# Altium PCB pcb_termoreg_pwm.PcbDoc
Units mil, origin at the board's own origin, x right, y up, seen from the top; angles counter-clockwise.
Board outline 1865 x 1535 mil, 2 copper layers (Top Layer, Bottom Layer); 28 components, 21 nets, 79 pads, 0 vias.
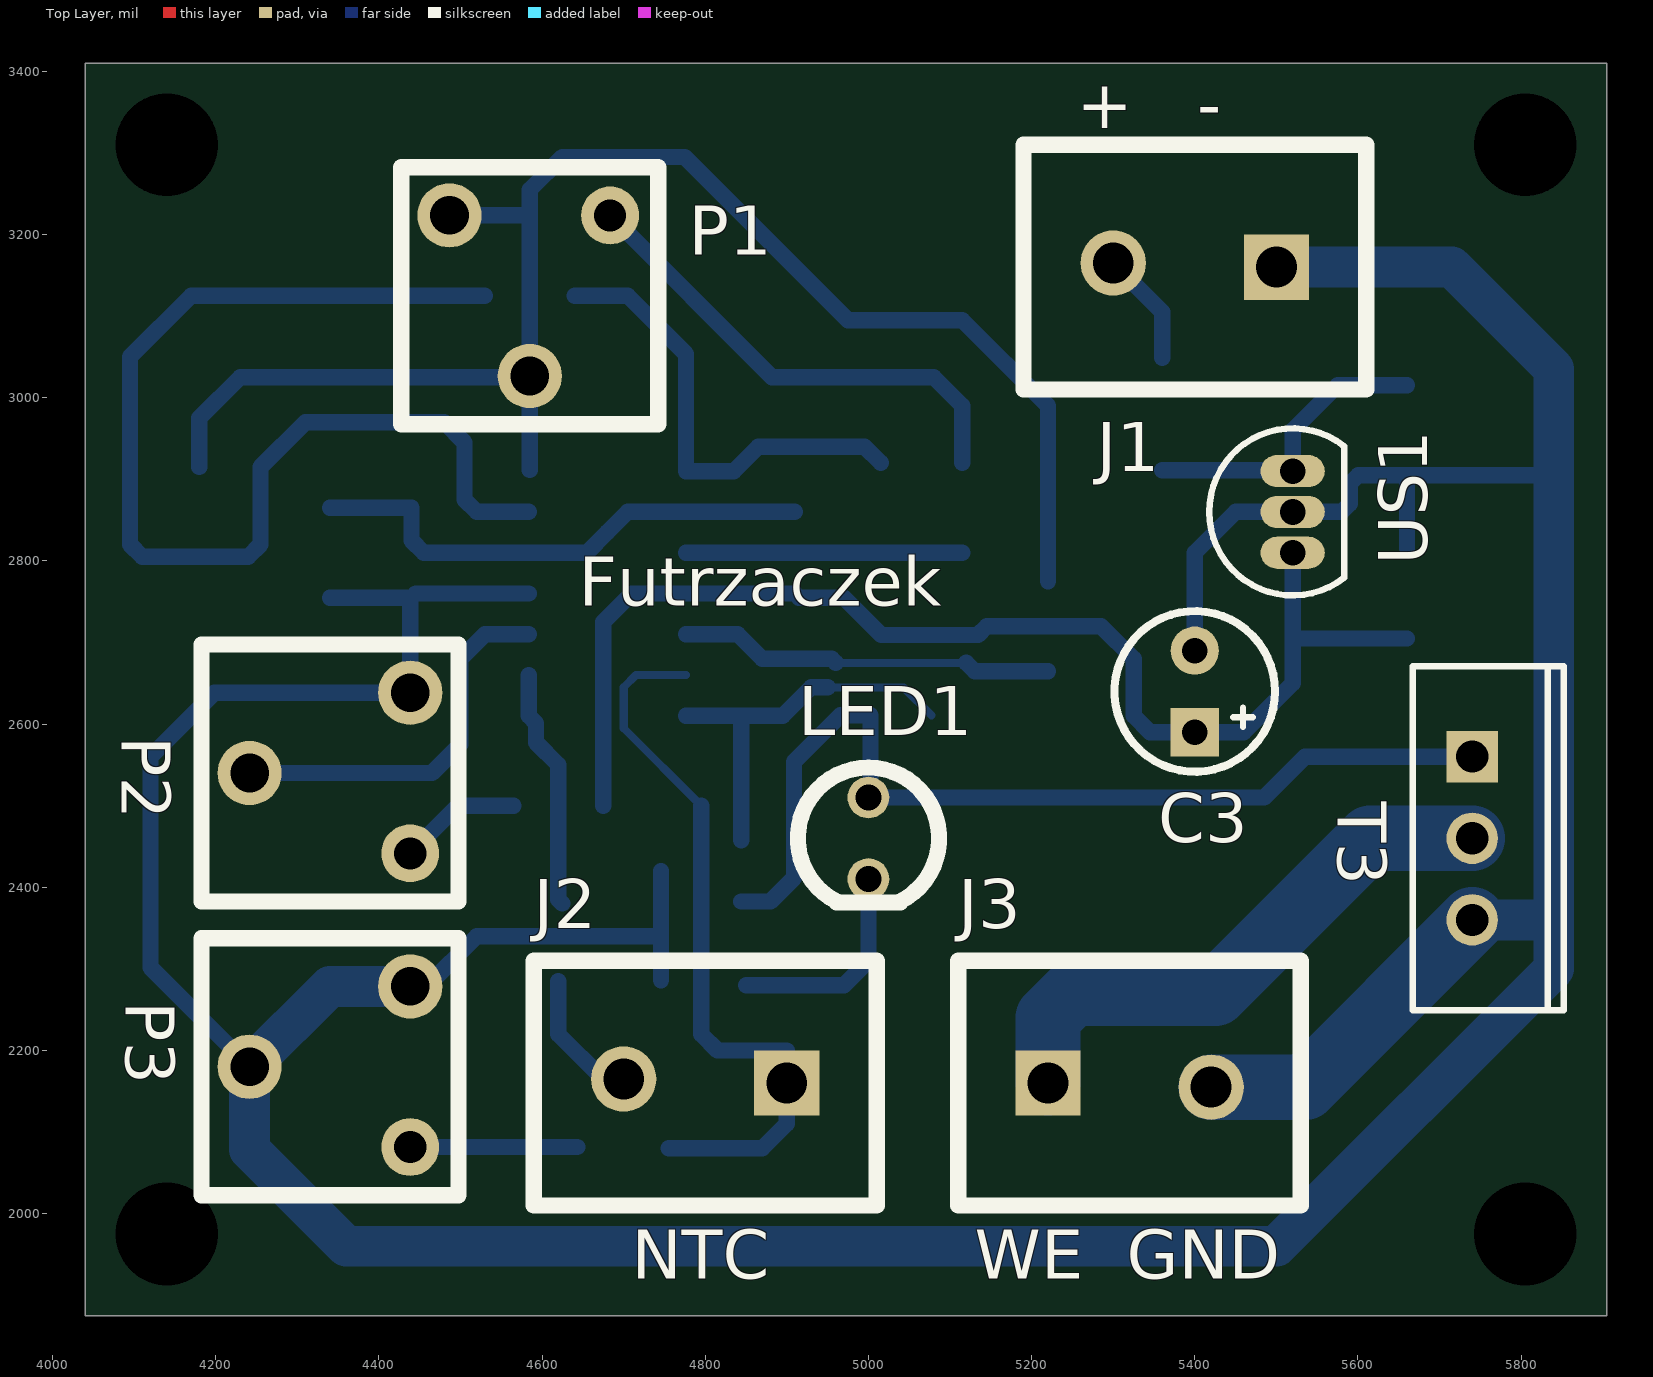
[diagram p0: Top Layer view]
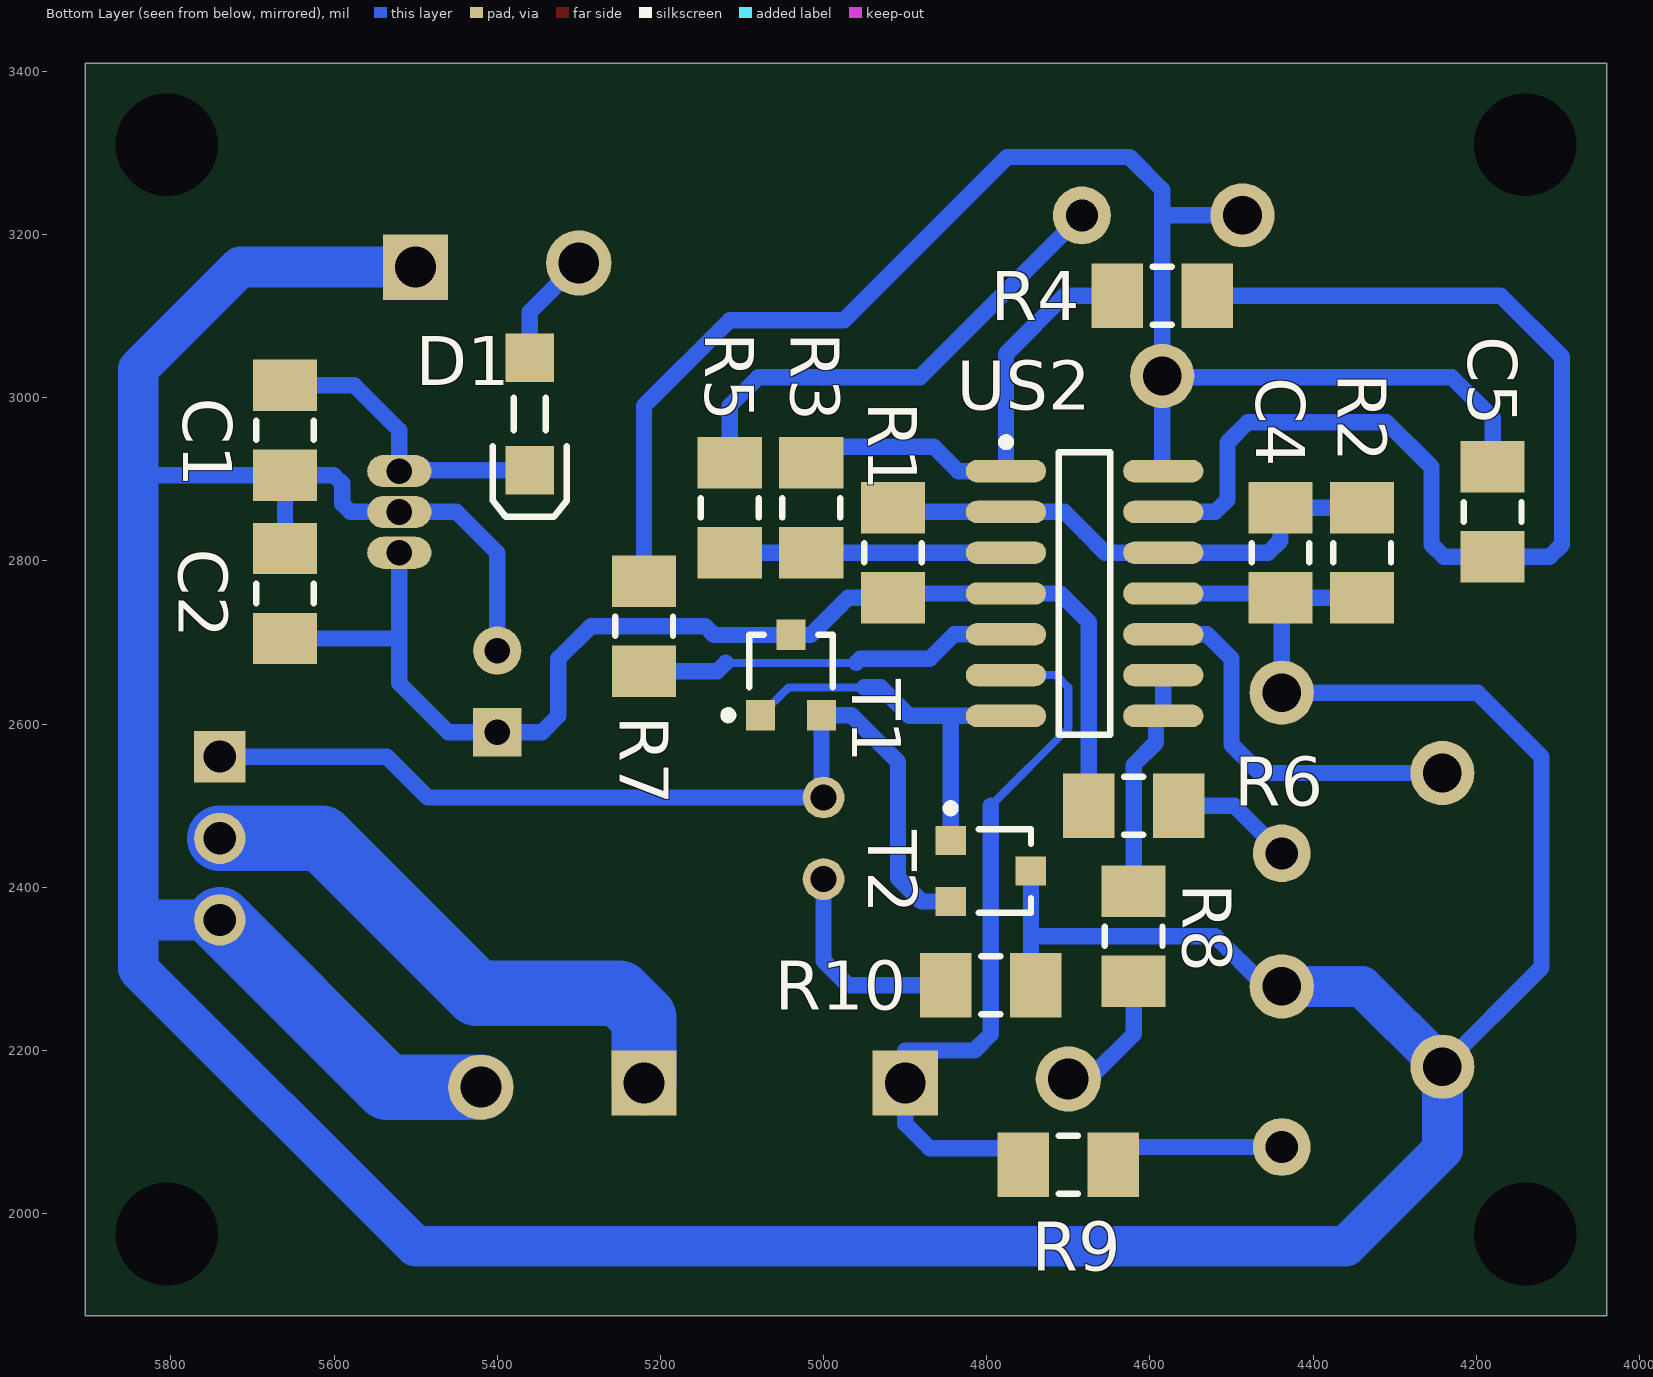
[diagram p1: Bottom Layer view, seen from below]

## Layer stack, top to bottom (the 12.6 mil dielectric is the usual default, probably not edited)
Top Layer: signal copper 1.4
Dielectric: dielectric 12.6, FR-4, Dk 4.8
Bottom Layer: signal copper 1.4

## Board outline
4040,1875 4040,3410 5905,3410 5905,1875

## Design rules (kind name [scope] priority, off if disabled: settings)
Clearance [All] p1: gap=10
PolygonConnect [All] p1: connectstyle=Relief reliefconductorwidth=10 reliefentries=4 polygonreliefangle="90 Angle"
RoutingVias [All] p1: holewidth=28 width=50 viastyle="Through Hole" minholewidth=28 minwidth=50 maxholewidth=28 maxwidth=50
SilkscreenOverComponentPads [All] p1: minsilkscreentomaskgap=10
SolderMaskExpansion [All] p1: expansion=4
Width [All] p1: maxlimit=100 minlimit=10 preferedwidth=20
27 further rules are at their usual default settings.

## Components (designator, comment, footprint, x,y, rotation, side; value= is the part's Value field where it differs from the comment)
C1 "100n" MELF-1206 5660,2960 r90 bottom
C2 "100n" MELF-1206 5660,2760 r270 bottom
C3 "220u/16V" "2,5/5mm elektrolit" 5400,2640 r90 top
C4 "100n" MELF-1206 4440,2810 r90 bottom
C5 "100n" MELF-1206 4180,2860 r270 bottom
D1 "1N4148" "dioda MINIMELF" 5360,2980 r270 bottom
J1 "ARK2" "ARK2 5mm" 5400,3160 r180 top
J2 "ARK2" "ARK2 5mm" 4800,2160 r180 top
J3 "ARK2" "ARK2 5mm" 5320,2160 r0 top
LED1 "green 3mm" "LED 3mm" 5000,2460 r90 top
P1 "100k" "pot mont poziom" 4585,3125 r180 top
P2 "100k" "pot mont poziom" 4340,2540 r90 top
P3 "100k" "pot mont poziom" 4340,2180 r90 top
R1 "100k" MELF-1206 4914.88,2810 r270 bottom
R2 "100k" MELF-1206 4340,2810 r270 bottom
R3 "100k" MELF-1206 5015,2865 r90 bottom
R4 "100k" MELF-1206 4585,3125 r180 bottom
R5 "10k" MELF-1206 5115,2865 r90 bottom
R6 "1k" MELF-1206 4620,2500 r180 bottom
R7 "0" MELF-1206 5220,2720 r90 bottom
R8 "1k" MELF-1206 4620,2340 r90 bottom
R9 "1k" MELF-1206 4700,2060 r180 bottom
R10 "1k" MELF-1206 4795,2280 r180 bottom
T1 "BC846" 318-08 5040,2660 r180 bottom
T2 "BC856" 318-08 4795,2420 r270 bottom
T3 "IRF540" TO-220AB 5740,2460 r270 top
US1 "78L09" 29-04 5520,2860 r0 top
US2 "LM324D" 751A-02_M 4680,2760 r180 bottom

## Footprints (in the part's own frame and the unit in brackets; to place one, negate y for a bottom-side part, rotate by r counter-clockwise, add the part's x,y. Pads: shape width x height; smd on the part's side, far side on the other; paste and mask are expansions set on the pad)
"2,5/5mm elektrolit" [mm]
  rect 1.5x1.5 hole 0.8: 1(-1.27,0)
  round 1.5 hole 0.8: 2(1.27,0)
  silkscreen extent -2.5,-2.5 2.5,2.5
29-04 [mm] "TO, Flat Index; 3 In-Line, Axial Leads; Body Dia. 4.8mm; Leads 0.48 x 0.5 mm (max)"
  oval 2x1 hole 0.8: 1(0,-1.27) 2(0,0) 3(0,1.27)
  silkscreen extent -2.6,-2.6 1.6,2.6
318-08 [mm] "SOT-23; 3 Leads; Body 3.0 x 2.6 mm, inc. leads (LxW max)"
  rect 0.9x0.95 smd: 1(-0.95,-1.25) 2(0.95,-1.25) 3(0,1.25)
  silkscreen extent -2.08,-1.37 1.3,1.25
751A-02_M [mm] "SOIC, 14-Leads, Body 8.7x3.9mm, Pitch 1.27mm, IPC Low Density"
  oval 2.5x0.7 smd: 1(-2.45,3.81) 2(-2.45,2.54) 3(-2.45,1.27) 4(-2.45,0) 5(-2.45,-1.27) 6(-2.45,-2.54) 7(-2.45,-3.81) 8(2.45,-3.81) 9(2.45,-2.54) 10(2.45,-1.27) 11(2.45,0) 12(2.45,1.27) 13(2.45,2.54) 14(2.45,3.81)
  silkscreen extent -2.58,-4.4 0.8,4.83, body extent -2,-4.38 2,4.38, height 1.75
"ARK2 5mm" [mil]
  rect 80x80 hole 50: 1(-100,0)
  round 80 hole 50: 2(100,-5)
  silkscreen extent -210,-150 210,150, body extent -220,-160 220,160, height 394
"dioda MINIMELF" [mm] "SMT LED; 2 Flat Leads"
  rect 1.5x1.5 smd: 1(-1.75,0) 2(1.75,0)
  silkscreen extent -0.5,-1.15 3.2,1.15
"LED 3mm" [mm]
  round 1.3 hole 0.8: A(1.27,0) K(-1.27,0)
  silkscreen extent -2,-2.2 2.2,2.2
MELF-1206 [mm] "Metal Electrode Face (MELF) Resistor; Body 3.2 x 1.8 mm (LxDia)"
  rect 1.6x2 smd: 1(-1.4,0) 2(1.4,0)
  silkscreen extent -0.3,-0.9 0.3,0.9, body extent -2.3,-1.1 2.3,1.1, height 1.85
"pot mont poziom" [mm]
  round 1.8 hole 1: a(-2.5,-2.5)
  round 2 hole 1.2: b(2.5,-2.5) c(0,2.5)
  silkscreen extent -4,-4 4,4
TO-220AB [mm] "TO, Thru-Hole, Vertical, Heatsink Mounted; 3 In-Line Leads; Pitch 2.54 mm"
  rect 1.6x1.6 hole 1: 1(-2.54,0)
  round 1.6 hole 1: 2(0,0) 3(2.54,0)
  silkscreen extent -5.35,-1.85 5.35,2.85

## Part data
C1 C2 C4 C5: library part kondensator
C3: library part "kond biegunowy", "Polarized Capacitor"
D1: library part Diode, "Default Diode"
LED1: library part LED
P1 P2 P3: library part "pot mont"
R1 R2 R3 R4 R5 R6 R7 R8 R9 R10: library part rezystor
T1: library part BC846BLT1, "General Purpose Transistor NPN Silicon"
T2: library part BC856ALT1, "General Purpose Transistor PNP Silicon"
T3: "HEXFET N-Channel Power MOSFET"
US1: library part MC78L05CP, "3-Terminal Low-Current Positive Fixed Voltage Regulator"
US2: "Quad Low-Power Operational Amplifier"

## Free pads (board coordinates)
  round 0 hole 125.98: 0(4140,1975) 1(5805,1975) 2(5805,3310) 3(4140,3310)

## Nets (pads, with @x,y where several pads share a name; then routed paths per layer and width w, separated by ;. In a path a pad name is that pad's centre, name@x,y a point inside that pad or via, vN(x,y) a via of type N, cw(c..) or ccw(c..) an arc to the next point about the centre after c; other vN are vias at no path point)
+4,5V: C4.2 R1.1 R2.1 US2.2 US2.12 | length 636.8
  Bottom Layer w20: R2.1 C4.2 4440,2825 4455,2810 US2.12 4655,2810 4680,2835 4705,2860 US2.2 R1.1@4909.76,2860
+9V: C2.2 C3.1 R1.2 R6.1 T1.3 US1.1 US2.4 | length 1582.5
  Bottom Layer w20: R6.1 4675.12,2725.12 4710,2760 US2.4 R1.2@4909.76,2760 ; R1.2 4970.12,2754.88 5015.79,2709.21 T1.3 5134.21,2709.21 5145,2720 5285,2720 5325,2680 5325,2610 5345,2590 C3.1 5460,2590 5520,2650 5520,2704.88 ; 5520,2765 5520,2704.88 ; US1.1 5520,2704.88 ; C2.2 5520,2704.88
GND: C1.1 C2.1 C3.2 C4.1 J1.1 J3.2 P2.b P3.b P3.c R2.2 R10.2 T2.3 T3.3 US1.2 US2.11 | length 6059.2
  Bottom Layer w20: P3.c 4120,2301.57 4120,2560 4198.43,2638.43 P2.b C4.1@4438.43,2753.31 ; R2.2 C4.1 ; P3.b 4458.43,2278.43 4520,2340 4745.79,2340 ; C4.1@4445.12,2760 US2.11 ; R10.2@4745.79,2285.91 4745.79,2340 ; T2.3 4745.79,2340 ; C3.2 5400,2810 5450,2860 US1.2 5580,2860 5590,2870 5590,2894.76 5600.12,2904.88 C1.1 ; C2.1 C1.1 ; 5834.88,2904.88 C1.1
  Bottom Layer w50: P3.b 4340,2278.43 P3.c 4241.57,2078.43 4360,1960 5500,1960 5840,2300 5840,2360 ; J1.1 5715,3160 5840,3035 5840,2360 ; T3.3 5840,2360
  Bottom Layer w80: J3.2 5535,2155 T3.3
NetC1_2: C1.2 D1.2 US1.3 | length 371.7
  Bottom Layer w20: D1.2 US1.3@5518.9,2911.1 ; US1.3 5520,2960 5575.12,3015.12 C1.2
NetC5_1: C5.1 P1.b P1.c R7.2 US2.14 | length 1920.3
  Bottom Layer w20: C5.1 4180,2975 4230,3025 P1.c@4585,3025 ; P1.b 4585,3223.43 ; US2.14@4585,2911.46 P1.c 4585,3255 4625,3295 4775,3295 4975,3095 5115,3095 5220,2990 R7.2
NetC5_2: C5.2 R4.2 US2.13 | length 1401.4
  Bottom Layer w20: R4.2 4170,3125 4095,3050 4095,2820 4110.12,2804.88 C5.2 4239.88,2804.88 4255,2820 4255,2915 4310,2970 4480,2970 4505,2945 4505,2875 4520,2860 US2.13
NetD1_1: D1.1 J1.2 | length 141
  Bottom Layer w20: J1.2 5360,3105 D1.1
NetJ2_1: J2.1 R9.1 US2.6 | length 907.5
  Bottom Layer w10: US2.6 4715,2660 4700.12,2645.12 4700.12,2594.88 4795,2500
  Bottom Layer w20: R9.1@4755.12,2080 4870,2080 4900,2110 4900,2200 4815,2200 4795,2220 4795,2500
NetJ2_2: J2.2 R8.1 | length 167.7
  Bottom Layer w20: R8.1 4620,2220 4675,2165 J2.2
NetJ3_1: J3.1 T3.2 | length 691.1
  Bottom Layer w80: J3.1 5220,2240 5250,2270 5425,2270 5615,2460 T3.2
NetLED1_A: LED1.A T1.2 T2.2 T3.1 | length 1198.9
  Bottom Layer w20: T2.2 4880,2382.6 4908.8,2411.4 4908.8,2553.8 4965.79,2610.79 T1.2 5002.6,2512.6 LED1.A 5485,2510 5535,2560 T3.1
NetLED1_K: LED1.K R10.1 | length 262.3
  Bottom Layer w20: R10.1 4970,2280 5000,2310 LED1.K
NetP1_a: P1.a R5.2 | length 598.1
  Bottom Layer w20: P1.a 4881.85,3025 4971.85,3025 5080,3025 5115,2990 R5.2
NetP2_a: P2.a R6.2 | length 150.7
  Bottom Layer w20: P2.a 4496.85,2500 R6.2
NetP2_c: P2.c US2.10 | length 473.9
  Bottom Layer w20: P2.c 4465,2540 4500,2575 4500,2680 4530,2710 US2.10
NetP3_a: P3.a R9.2 | length 204.9
  Bottom Layer w20: P3.a R9.2@4643.31,2081.57
NetR3_1: R3.1 R5.1 US2.3 | length 338.5
  Bottom Layer w20: US2.3 R3.1@5015,2810 ; R3.1 R5.1
NetR3_2: R3.2 R4.1 US2.1 | length 568.7
  Bottom Layer w20: R4.1 4705,3125 4776.46,3053.54 US2.1 4835,2910 4865,2940 4995.12,2940 R3.2
NetR7_1: R7.1 US2.5 | length 462.2
  Bottom Layer w10: 4960,2675 4980,2675 5120,2675
  Bottom Layer w20: US2.5 4840,2710 4870,2680 4955,2680 4960,2675 ; 5120,2675 5130.12,2664.88 R7.1
NetR8_2: R8.2 US2.8 US2.9 | length 297.1
  Bottom Layer w20: US2.9 US2.8 4592.58,2600.97 4592.58,2577.42 4620,2550 R8.2 4620,2384.88 R8.2@4624.88,2380
NetT1_1: T1.1 T2.1 US2.7 | length 482.2
  Bottom Layer w10: 4950,2645 5043.19,2645 T1.1
  Bottom Layer w20: US2.7 4844.21,2610 ; T2.1 4844.21,2610 ; 4950,2645 4930,2645 4895,2610 4844.21,2610

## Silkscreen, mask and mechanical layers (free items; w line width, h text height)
Top Overlay:
  text "+   -" at 5255,3330 h60
  text "Futrzaczek" at 4645,2745 h60
  text "NTC" at 4710,1920 h60
  text "WE  GND" at 5130,1920 h60
Mechanical 1:
  the board outline again, w10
